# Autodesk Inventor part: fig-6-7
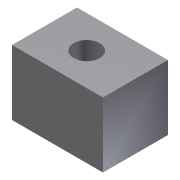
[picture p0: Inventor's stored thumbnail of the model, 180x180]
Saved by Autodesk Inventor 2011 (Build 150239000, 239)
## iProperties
Created: 2009-09
Part Number: fig-6-7
Document SubType Name: Modeling
Designer: Sham
Density: 1 g/cm^3
Author: Sham
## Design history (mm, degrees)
sketch "Sketch1"
  geometry: L1 (-28, 20)-(0, 20); L2 (0, 20)-(0, 0); L3 (0, 0)-(-28, 0); L4 (-28, 0)-(-28, 20)
  constraints: 8 end point, 2 parallel, 1 horizontal, 1 perpendicular
extrude "Extrusion1" new body sketch "Sketch1" distance "d0" = 20; taper "d1" = 0 deg
hole "Hole1" diameter "d4" = 8; stored, may be unused: countersink angle "d8" = 90 deg, drill point angle "d10" = 118 deg; dims "d2" = 10, "d3" = 15, "d5" = 6, "d6" = 4, "d7" = 2, "d9" = 15
body "Solid1"
